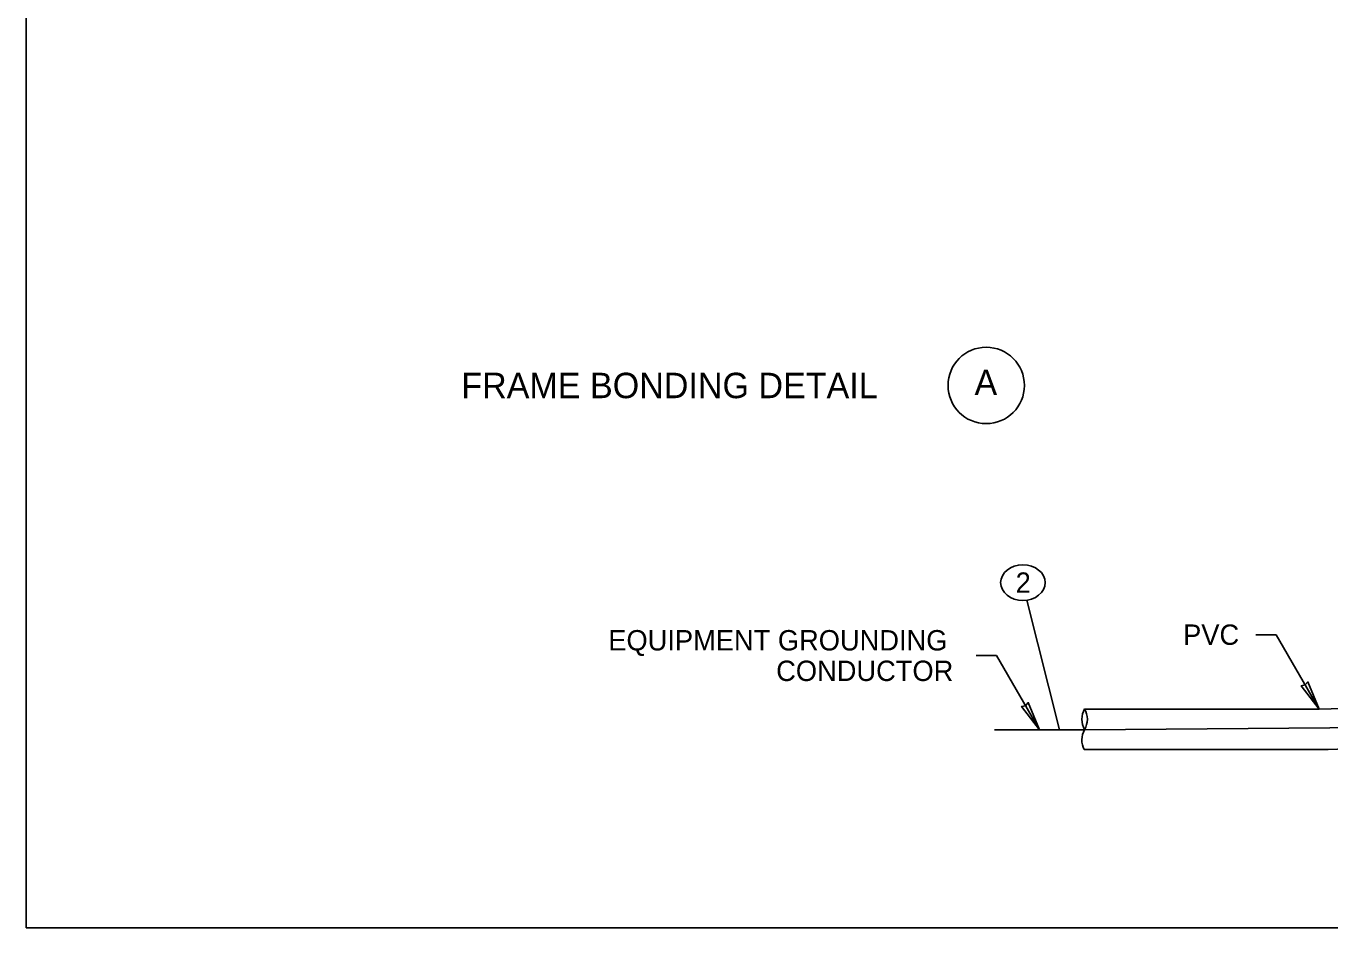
# Model space of a CAD drawing. Extents: x 99862 to 103151, y 100000 to 102076.
# Drawn here: x 99862 to 100886, y 100000 to 100708 of the extents above; entities that cross this region are included whole.
import ezdxf

# ---------------------------------------------------------------- set-up
doc = ezdxf.new("R2010")
doc.units = 0
for name, color, linetype in [('Level 1', 7, 'Continuous'), ('Level 12', 7, 'Continuous'), ('Level 13', 7, 'Continuous'), ('Level 15', 7, 'Continuous'), ('Level 20', 7, 'Continuous'), ('Level 60', 7, 'Continuous')]:
    doc.layers.add(name, color=color, linetype=linetype)

msp = doc.modelspace()

# ---------------------------------------------------------------- linework, layer by layer
at = {"layer": 'Level 1'}
msp.add_lwpolyline([(99862, 99999.5), (103151, 99999.5), (103151, 102075.5), (99862, 102075.5)], close=True, dxfattribs=at)
at = {"layer": 'Level 12'}
for q in [(100622.2, 100155.2), (100885.6, 100156.6)]:
    msp.add_line((100693, 100155.2), q, dxfattribs=at)
msp.add_arc((100880.8, 100550.2), 393.6, 270.6995, 0.6995, dxfattribs=at)
at = {"layer": 'Level 13'}
for p, q in [((100693, 100171.5), (100877.2, 100171.5)), ((100692.6, 100139.6), (100877.2, 100139.6))]:
    msp.add_line(p, q, dxfattribs=at)
for radius, end in [(414.4, 301.4523), (382.5, 292.4573)]:
    msp.add_arc((100877.2, 100554), radius, 270, end, dxfattribs=at)
at = {"layer": 'Level 15'}
for p, q in [((100647.7, 100257), (100673.3, 100155.2)), ((100827.5, 100229.9), (100843.5, 100229.9)), ((100877.2, 100171.5), (100843.5, 100229.9)), ((100607.9, 100213.5), (100623.9, 100213.5)), ((100657.6, 100155.2), (100623.9, 100213.5))]:
    msp.add_line(p, q, dxfattribs=at)
for points in [[(100877.2, 100171.5), (100863.2, 100189.8), (100866.3, 100190.4), (100868.4, 100192.8)], [(100657.6, 100155.2), (100643.6, 100173.5), (100646.7, 100174.1), (100648.8, 100176.5)]]:
    msp.add_lwpolyline(points, close=True, dxfattribs=at)
for centre, start, end in [((100707.2, 100163.4), 150, 210), ((100678.9, 100163.4), 330, 30), ((100707.2, 100147), 150, 206.9934)]:
    msp.add_arc(centre, 16.3, start, end, dxfattribs=at)
at = {"layer": 'Level 20'}
msp.add_circle((100615.8, 100425.7), 30, dxfattribs=at)
msp.add_ellipse((100644.6, 100270.8), major_axis=(-17.5, 0), ratio=0.8, dxfattribs=at)
at = {"layer": 'Level 60'}
msp.add_line((99862, 99999.5), (99862, 99999.5), dxfattribs=at)

# ---------------------------------------------------------------- texts
at = {"layer": 'Level 20'}
for s, height, p in [('FRAME BONDING DETAIL', 20, (100203.7, 100415.7)), ('A', 20, (100606.6, 100418.1)), ('2', 16, (100638.9, 100262.8)), ('PVC', 16, (100770.4, 100221.9)), ('EQUIPMENT GROUNDING', 16, (100319.1, 100217.5)), ('CONDUCTOR', 16, (100450.9, 100193.5))]:
    msp.add_text(s, height=height, dxfattribs=at).set_placement(p)

doc.saveas('drawing.dxf')
